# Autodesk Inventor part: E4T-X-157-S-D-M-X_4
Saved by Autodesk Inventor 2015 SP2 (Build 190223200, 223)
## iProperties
Created: 2016-05
Part Number: E4T-X-157-S-D-M-X_4
Material: Allgemein
Document SubType Name: Modeling
Designer: ryll
Density: 1 g/cm^3
Appearance: Vorgabe
Author: ryll
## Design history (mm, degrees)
node "E4T-X-157-S-D-M-X_41"
node "E4T-X-157-S-D-M-X_4"
node "Basis1"
